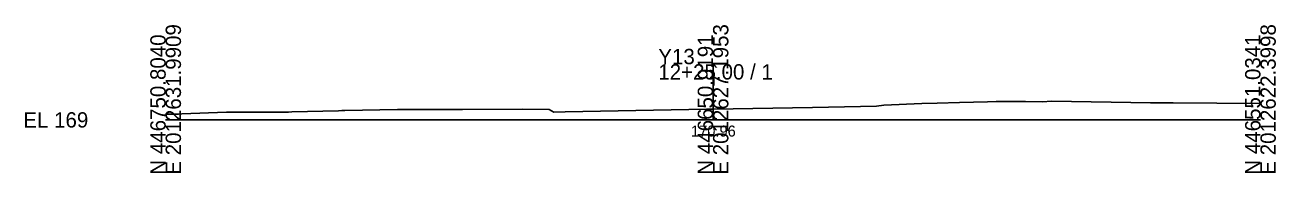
# Model space of a CAD drawing. Extents: x -26 to 1403, y -10 to 4517.
# Drawn here: x -25.7 to 202.8, y 4490.3 to 4517.3 of the extents above; entities that cross this region are included whole.
import ezdxf

# ---------------------------------------------------------------- set-up
doc = ezdxf.new("R2010")
doc.units = 0
for name, color, linetype in [('Default', 7, 'Continuous'), ('Exist Cross Section Cell', 7, 'Continuous'), ('Exist XS Center Line Elevation Label', 7, 'Continuous'), ('Exist XS Ground Line', 7, 'Continuous')]:
    doc.layers.add(name, color=color, linetype=linetype)

msp = doc.modelspace()

# ---------------------------------------------------------------- linework, layer by layer
at = {"layer": 'Exist Cross Section Cell'}
for p, q in [((100, 4500), (100, 4510.17)), ((0, 4500), (100, 4500)), ((100, 4500), (200, 4500))]:
    msp.add_line(p, q, dxfattribs=at)
at = {"layer": 'Exist XS Ground Line'}
msp.add_lwpolyline([(0, 4501.04), (1.07, 4501.05), (1.68, 4501.06), (2.32, 4501.07), (2.95, 4501.08), (11.09, 4501.4), (11.57, 4501.41), (12.01, 4501.41), (12.4, 4501.42), (12.79, 4501.43), (21.1, 4501.42), (21.47, 4501.42), (21.91, 4501.43), (22.45, 4501.44), (23.08, 4501.46), (31.55, 4501.68), (32.16, 4501.69), (32.72, 4501.7), (42.34, 4501.9), (51.48, 4501.91), (54.23, 4501.92), (65.16, 4501.98), (70.07, 4501.87), (70.93, 4501.42), (73, 4501.47), (98.8, 4501.97), (100, 4501.96), (118.19, 4502.24), (129.89, 4502.52), (131.23, 4502.67), (138.14, 4503.01), (140.92, 4503.04), (145, 4503.18), (150.16, 4503.3), (151.74, 4503.33), (157.11, 4503.33), (160.14, 4503.3), (161.9, 4503.39), (179.9, 4503.11), (181.92, 4503.1), (184.04, 4503.1), (200, 4503.01)], dxfattribs=at)

# ---------------------------------------------------------------- texts
at = {"layer": 'Default'}
msp.add_text('-', height=0.0001, dxfattribs=at).set_placement((0, 4500))
at = {"layer": 'Exist Cross Section Cell'}
for s, p in [('E 2012631.9909', (2.8, 4490)), ('E 2012627.1953', (102.8, 4490)), ('E 2012622.3998', (202.8, 4490)), ('N 446750.8040', (0, 4490)), ('N 446650.9191', (100, 4490)), ('N 446551.0341', (200, 4490))]:
    msp.add_text(s, height=2.8, rotation=90, dxfattribs=at).set_placement(p)
for s, p in [('Y13', (90, 4510.17)), ('12+25.00 / 1', (90, 4507.37)), ('EL 169', (-26, 4498.6))]:
    msp.add_text(s, height=2.8, dxfattribs=at).set_placement(p)
at = {"layer": 'Exist XS Center Line Elevation Label'}
msp.add_text('170.96', height=2, dxfattribs=at).set_placement((95.97, 4496.96))

doc.saveas('drawing.dxf')
